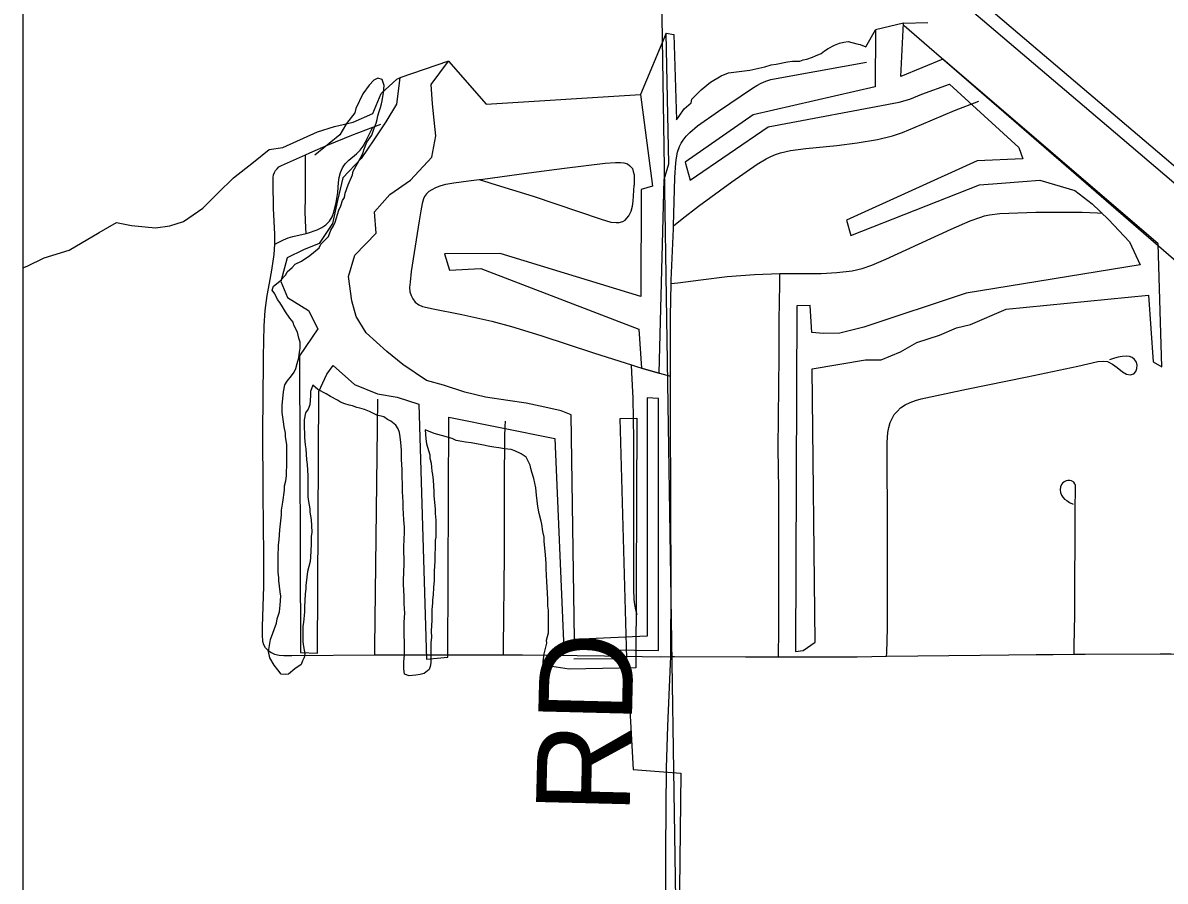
# Model space of a CAD drawing. Extents: x 0 to 34, y 0 to 22.
# Drawn here: x 2.1 to 2.4461, y 18.0054 to 18.2654 of the extents above; entities that cross this region are included whole.
import ezdxf

# ---------------------------------------------------------------- set-up
doc = ezdxf.new("R2010")
doc.units = 0
for name, color, linetype in [('GM_X_Corporation', 7, 'Continuous'), ('GM_X_Major_River', 7, 'Continuous'), ('GM_X_Minor_River', 7, 'Continuous'), ('GM_X_State_Route', 7, 'Continuous'), ('GM_X_Township_Road', 7, 'Continuous'), ('GM_X_Township_Road_Text', 7, 'Continuous')]:
    doc.layers.add(name, color=color, linetype=linetype)

msp = doc.modelspace()

# ---------------------------------------------------------------- linework, layer by layer
at = {"layer": 'GM_X_Corporation'}
for points in [[(2.1, 19.23555), (2.1, 16.59135)], [(3.00478, 18.43707), (2.97992, 18.42919), (2.92938, 18.42252), (2.66141, 18.41843), (2.5349, 18.41088), (2.48912, 18.40358), (2.36749, 18.37012), (2.29892, 18.34983), (2.2944, 18.34848), (2.29017, 18.34722), (2.28004, 18.34423), (2.20498, 18.31695), (2.13026, 18.28436), (2.1, 18.27405), (2.1, 16.59135)]]:
    msp.add_lwpolyline(points, dxfattribs=at)
for points in [[(2.1, 18.4508), (2.1, 17.94805), (2.29863, 17.94779), (2.29081, 18.44969)], [(2.29081, 18.44969), (2.80234, 18.44894), (2.79974, 17.94803), (2.29863, 17.94779)]]:
    msp.add_lwpolyline(points, close=True, dxfattribs=at)
at = {"layer": 'GM_X_Major_River'}
for p, q in [((2.29485, 18.26222), (2.28712, 18.24365)), ((2.36683, 18.26533), (2.35828, 18.2633)), ((2.22891, 18.25375), (2.21425, 18.24872))]:
    msp.add_line(p, q, dxfattribs=at)
for points in [[(2.36683, 18.26533), (2.37415, 18.26545)], [(2.28712, 18.24365), (2.29072, 18.21589), (2.28729, 18.21496), (2.28725, 18.18247), (2.24462, 18.1955), (2.22772, 18.19542), (2.22921, 18.19047), (2.2387, 18.19098), (2.28661, 18.17259), (2.28747, 18.16081), (2.29278, 18.15925), (2.29434, 18.21795), (2.2957, 18.22269), (2.29485, 18.26222)], [(2.29485, 18.26222), (2.29718, 18.26184), (2.298, 18.23604)], [(2.35825, 18.24599), (2.32125, 18.23753), (2.30065, 18.22323), (2.30212, 18.21771), (2.32579, 18.23389), (2.36552, 18.2414), (2.36876, 18.24233), (2.37238, 18.24382), (2.38075, 18.2468), (2.40169, 18.22766), (2.40299, 18.22423), (2.38913, 18.22357), (2.3495, 18.2056), (2.3508, 18.20103), (2.38983, 18.21634), (2.39648, 18.21686), (2.40294, 18.21739), (2.40807, 18.21773), (2.41868, 18.21462), (2.42397, 18.21059), (2.42887, 18.20581), (2.43527, 18.19911), (2.43845, 18.19206), (2.3858, 18.1835), (2.35477, 18.17326), (2.34755, 18.17141), (2.34261, 18.17126), (2.339, 18.17166), (2.33849, 18.17983), (2.3345, 18.17967), (2.33412, 18.07498), (2.33641, 18.07534), (2.34003, 18.07779), (2.33911, 18.16064), (2.35527, 18.16338), (2.36002, 18.16334), (2.36592, 18.16577), (2.37088, 18.16859), (2.37773, 18.17082), (2.38287, 18.17307), (2.38706, 18.17399), (2.39791, 18.17866), (2.44104, 18.18292), (2.44242, 18.16277), (2.44506, 18.16123), (2.444, 18.19848), (2.37872, 18.25442), (2.36596, 18.24919), (2.36683, 18.26533)], [(2.31154, 18.24933), (2.31381, 18.2503), (2.31704, 18.25069), (2.32026, 18.25109), (2.32386, 18.25186), (2.32481, 18.25206), (2.32671, 18.25264), (2.32823, 18.25283), (2.33164, 18.25361), (2.33316, 18.25381), (2.33543, 18.25382), (2.33638, 18.2542), (2.33752, 18.2544), (2.33922, 18.25498), (2.34017, 18.25536), (2.34188, 18.25613), (2.34282, 18.25689), (2.34396, 18.25766), (2.34585, 18.25862), (2.34737, 18.2592), (2.34869, 18.25958), (2.35002, 18.25978), (2.35268, 18.25903), (2.35363, 18.25885), (2.35534, 18.25809), (2.35828, 18.2633)], [(2.35828, 18.2633), (2.35825, 18.24599)], [(2.2661, 18.14671), (2.26307, 18.14787), (2.25815, 18.14904), (2.25246, 18.15022), (2.24696, 18.15102), (2.24013, 18.15202), (2.23388, 18.15358), (2.22744, 18.15571), (2.22232, 18.15708), (2.21514, 18.16188), (2.21023, 18.1659), (2.20401, 18.17146), (2.201, 18.17642), (2.19971, 18.18118), (2.19863, 18.18859), (2.20057, 18.19504), (2.20707, 18.20165), (2.20655, 18.20811), (2.21115, 18.2134), (2.21744, 18.21773), (2.22395, 18.22471), (2.22514, 18.23116), (2.2246, 18.23592), (2.22407, 18.24086), (2.22373, 18.24675), (2.22891, 18.25375)], [(2.22891, 18.25375), (2.24039, 18.24075), (2.28712, 18.24365)], [(2.21425, 18.24872), (2.21324, 18.24075), (2.20998, 18.23545), (2.20633, 18.22996), (2.20249, 18.22429), (2.19694, 18.21844), (2.19537, 18.21161), (2.1938, 18.20459), (2.18977, 18.19854), (2.18501, 18.19667), (2.18006, 18.19423), (2.17811, 18.18703), (2.18016, 18.18226), (2.18659, 18.17823), (2.1894, 18.1727)], [(2.18926, 18.23236), (2.1944, 18.23404), (2.2001, 18.23533), (2.20601, 18.23795), (2.20852, 18.24401), (2.21332, 18.2483), (2.21425, 18.24872)], [(2.298, 18.23604), (2.29888, 18.23711), (2.30039, 18.2394), (2.30247, 18.24112), (2.30265, 18.24226), (2.30548, 18.24513), (2.30832, 18.24742), (2.31154, 18.24933)], [(2.1, 18.19121), (2.10131, 18.19171), (2.10642, 18.1942), (2.114, 18.19652), (2.12309, 18.20188), (2.12839, 18.20495), (2.13295, 18.20402), (2.14016, 18.20329), (2.14453, 18.20389), (2.1487, 18.20524), (2.15456, 18.20925), (2.15909, 18.21384), (2.16382, 18.21842), (2.16987, 18.2232), (2.17459, 18.22702), (2.17877, 18.22761), (2.18926, 18.23236)], [(2.1894, 18.1727), (2.18383, 18.16457), (2.18413, 18.07469), (2.18925, 18.07446), (2.18964, 18.1537), (2.19214, 18.159), (2.19406, 18.16165), (2.20048, 18.1559), (2.20748, 18.153), (2.21336, 18.15201), (2.21999, 18.14987), (2.22228, 18.07272), (2.22874, 18.07324), (2.22907, 18.14601), (2.26112, 18.13952), (2.26388, 18.07566), (2.29255, 18.07527), (2.29253, 18.15165), (2.28911, 18.15187), (2.28916, 18.07966), (2.26713, 18.07868), (2.2661, 18.14671)]]:
    msp.add_lwpolyline(points, dxfattribs=at)
at = {"layer": 'GM_X_Minor_River'}
for points in [[(2.36701, 18.26457), (2.64872, 18.02059), (2.66169, 18.00811), (2.737, 17.94422), (2.75628, 17.92455), (2.77219, 17.89365), (2.65804, 17.86859), (2.54682, 17.86408), (2.47603, 17.86127), (2.42061, 17.8593)], [(2.17767, 18.10883), (2.17784, 18.11187), (2.17839, 18.11643), (2.17838, 18.11776), (2.17875, 18.12024), (2.1793, 18.12385), (2.17929, 18.12518), (2.17966, 18.1267), (2.17985, 18.12822), (2.18001, 18.1324), (2.17999, 18.13773), (2.17959, 18.14), (2.17959, 18.14114), (2.1792, 18.14304), (2.179, 18.14456), (2.17861, 18.14741), (2.1786, 18.1495), (2.17896, 18.15368), (2.17932, 18.15578), (2.18008, 18.15692), (2.1814, 18.15845), (2.18215, 18.15959), (2.18272, 18.16073), (2.18309, 18.16226), (2.18365, 18.16397), (2.18383, 18.16568), (2.18401, 18.16682), (2.184, 18.16872), (2.18362, 18.16986), (2.18323, 18.17176), (2.18208, 18.17384), (2.18188, 18.17479), (2.18093, 18.17593), (2.17959, 18.17782), (2.17863, 18.17934), (2.17787, 18.18067), (2.1771, 18.18161), (2.17634, 18.18332), (2.17557, 18.18446), (2.17594, 18.1856), (2.17783, 18.18713), (2.17972, 18.18904), (2.1801, 18.18999), (2.18161, 18.19133), (2.18255, 18.19228), (2.18445, 18.19324), (2.18691, 18.19496), (2.18974, 18.19726), (2.1903, 18.1984), (2.19257, 18.20069), (2.19332, 18.2026), (2.19407, 18.20393), (2.19464, 18.20507), (2.19576, 18.20869), (2.19632, 18.21002), (2.19688, 18.21154), (2.19745, 18.2125), (2.19763, 18.21383), (2.19857, 18.2163), (2.19988, 18.21935), (2.20006, 18.22049), (2.20138, 18.22278), (2.20307, 18.22602), (2.20326, 18.22697), (2.20419, 18.22925), (2.2057, 18.23135), (2.20645, 18.23345), (2.20701, 18.23497), (2.20739, 18.23611), (2.20757, 18.23725), (2.20794, 18.23858), (2.20832, 18.23973), (2.20869, 18.24087), (2.20888, 18.24182), (2.20924, 18.24429), (2.20942, 18.24638), (2.20884, 18.24828), (2.20751, 18.24865), (2.20638, 18.24808), (2.20487, 18.24655), (2.20298, 18.24388), (2.20091, 18.2395), (2.20054, 18.23817), (2.19809, 18.23493), (2.19677, 18.23264), (2.19602, 18.2315), (2.19489, 18.23054), (2.19394, 18.22977), (2.18843, 18.22532)], [(2.21544, 18.07195), (2.21562, 18.07385), (2.21557, 18.08392), (2.21575, 18.08658), (2.21554, 18.08943), (2.21553, 18.09171), (2.21532, 18.09532), (2.21532, 18.09646), (2.21548, 18.10159), (2.21546, 18.10673), (2.21562, 18.1111), (2.21561, 18.11262), (2.21541, 18.1149), (2.2152, 18.11851), (2.2152, 18.12022), (2.21499, 18.12345), (2.21496, 18.1301), (2.21475, 18.13314), (2.21473, 18.13599), (2.21453, 18.13827), (2.21434, 18.13998), (2.21414, 18.14131), (2.21375, 18.14245), (2.21299, 18.14358), (2.21146, 18.14472), (2.21051, 18.14528), (2.20937, 18.14604), (2.20728, 18.1466), (2.20499, 18.14773), (2.20347, 18.14829), (2.20214, 18.14866), (2.20119, 18.14885), (2.19986, 18.14941), (2.19891, 18.1496), (2.19758, 18.14997), (2.19625, 18.15054), (2.19529, 18.1511), (2.1932, 18.15223), (2.19187, 18.15299), (2.18939, 18.1543), (2.18787, 18.15563), (2.18712, 18.15372), (2.18713, 18.15239), (2.18695, 18.14973), (2.18639, 18.1484), (2.18563, 18.14725), (2.18526, 18.14516), (2.18527, 18.14402), (2.18529, 18.13984), (2.18549, 18.13756), (2.18569, 18.13642), (2.1859, 18.133), (2.18609, 18.13167), (2.1863, 18.12825), (2.18633, 18.12179), (2.18653, 18.12046), (2.18692, 18.11818), (2.18693, 18.11723), (2.18732, 18.11495), (2.18753, 18.11115), (2.18734, 18.10982), (2.18736, 18.10754), (2.18719, 18.10355), (2.187, 18.10222), (2.18626, 18.09918), (2.18608, 18.09746), (2.18571, 18.09499), (2.18572, 18.09404), (2.18554, 18.09233), (2.18537, 18.08853), (2.18537, 18.08701), (2.18501, 18.08378), (2.18483, 18.08263), (2.18484, 18.07921), (2.18485, 18.07788), (2.18505, 18.07655), (2.18544, 18.07428), (2.18525, 18.07313), (2.18469, 18.07218), (2.18432, 18.07104), (2.18242, 18.0697), (2.18053, 18.06817), (2.17959, 18.06798), (2.17826, 18.06816), (2.1773, 18.06948), (2.17615, 18.07081), (2.17481, 18.07308), (2.17443, 18.07498), (2.17498, 18.0786), (2.17685, 18.08355), (2.17703, 18.08488), (2.17778, 18.08697), (2.17796, 18.08906), (2.17813, 18.09173), (2.17794, 18.09305), (2.17754, 18.09647), (2.17754, 18.09742), (2.17734, 18.09894), (2.17731, 18.1035), (2.17749, 18.10731), (2.17767, 18.10883)], [(2.26691, 18.07276), (2.28302, 18.07284), (2.28094, 18.14561), (2.28606, 18.14564), (2.28569, 18.07), (2.2655, 18.06964)], [(2.2655, 18.06964), (2.25759, 18.07081), (2.25759, 18.07196), (2.25795, 18.07424), (2.2587, 18.07747), (2.25869, 18.07842), (2.25925, 18.0807), (2.25922, 18.08755), (2.25902, 18.08869), (2.25901, 18.09078), (2.2588, 18.09458), (2.25879, 18.0961), (2.25858, 18.10009), (2.25857, 18.10161), (2.25837, 18.10427), (2.25797, 18.10845), (2.25796, 18.10959), (2.25757, 18.1113), (2.25718, 18.11357), (2.25699, 18.11452), (2.25641, 18.1168), (2.25602, 18.11889), (2.25562, 18.12231), (2.25542, 18.12459), (2.25483, 18.12744), (2.25425, 18.12933), (2.25387, 18.13047), (2.25367, 18.13142), (2.25252, 18.13389), (2.251, 18.13483), (2.2491, 18.13577), (2.24796, 18.13615), (2.24587, 18.13633), (2.24416, 18.1367), (2.24264, 18.13688), (2.2415, 18.13707), (2.23903, 18.13762), (2.2358, 18.13818), (2.23409, 18.13836), (2.23295, 18.13855), (2.23124, 18.13892), (2.23009, 18.13948), (2.22686, 18.14042), (2.22458, 18.14098), (2.22192, 18.14211), (2.22212, 18.13945), (2.22232, 18.13793), (2.22329, 18.13451), (2.22329, 18.13356), (2.22368, 18.13204), (2.22388, 18.12957), (2.22408, 18.12862), (2.22427, 18.12691), (2.22448, 18.12349), (2.22449, 18.12216), (2.22489, 18.11817), (2.22489, 18.11684), (2.2251, 18.11475), (2.22512, 18.10962), (2.22494, 18.10867), (2.22495, 18.10696), (2.22477, 18.10373), (2.22478, 18.1024), (2.22461, 18.09936), (2.22462, 18.09651), (2.22444, 18.09441), (2.22426, 18.09213), (2.22408, 18.09061), (2.22409, 18.08966), (2.22391, 18.08776), (2.22392, 18.08453), (2.22375, 18.08111), (2.22376, 18.07921), (2.22358, 18.07769), (2.22361, 18.07161), (2.22343, 18.07046), (2.22305, 18.06951), (2.22154, 18.06836), (2.2204, 18.06798), (2.21907, 18.06778), (2.21699, 18.06758), (2.21565, 18.06815), (2.21545, 18.06986), (2.21544, 18.07195)], [(2.25939, 18.069), (2.25935, 18.06901)], [(2.28322, 18.06995), (2.2849, 18.03921), (2.29934, 18.03813), (2.29802, 17.9241)]]:
    msp.add_lwpolyline(points, dxfattribs=at)
at = {"layer": 'GM_X_State_Route'}
for points in [[(2.32715, 18.32565), (2.4035, 18.2607), (2.44374, 18.22642), (2.60957, 18.08537), (2.64991, 18.0512), (2.66881, 18.03502), (2.69927, 18.00908), (2.70884, 18.00091), (2.79294, 17.92908), (2.8025, 17.92113), (2.81117, 17.91424), (2.81841, 17.9089), (2.82651, 17.90318), (2.83267, 17.89916), (2.83668, 17.89664), (2.84237, 17.89321), (2.84916, 17.88924), (2.8572, 17.88476), (2.86534, 17.88048), (2.87342, 17.87642)], [(2.32427, 18.32289), (2.43302, 18.23041), (2.53238, 18.14581), (2.5762, 18.10862), (2.6425, 18.05228), (2.67326, 18.0261), (2.70357, 18.00047), (2.71553, 17.99031), (2.75061, 17.96052), (2.79287, 17.92439), (2.80271, 17.91643), (2.81262, 17.90855), (2.82077, 17.90255), (2.82865, 17.89695)]]:
    msp.add_lwpolyline(points, dxfattribs=at)
at = {"layer": 'GM_X_Township_Road'}
msp.add_line((2.20606, 18.23379), (2.20843, 18.23467), dxfattribs=at)
for points in [[(2.29944, 18.229), (2.30002, 18.22986), (2.30098, 18.23107), (2.30206, 18.23219), (2.30443, 18.23417), (2.31076, 18.23864), (2.32101, 18.24563), (2.32232, 18.24645), (2.32369, 18.24717), (2.32512, 18.24774), (2.3266, 18.24819), (2.33269, 18.24938), (2.35558, 18.25346)], [(2.29716, 18.20395), (2.29979, 18.20602), (2.30471, 18.20989), (2.3148, 18.21728), (2.32251, 18.22264), (2.3252, 18.22423), (2.3266, 18.22491), (2.32805, 18.22551), (2.32953, 18.22601), (2.33257, 18.22674), (2.33722, 18.2273), (2.34656, 18.22822), (2.35277, 18.22903), (2.35893, 18.23011), (2.36348, 18.23121), (2.36645, 18.23219), (2.37223, 18.23456), (2.38229, 18.23889), (2.38961, 18.24165)], [(2.18568, 18.22543), (2.18693, 18.22598), (2.19252, 18.22846), (2.1997, 18.23142), (2.20606, 18.23379)], [(2.18582, 18.20164), (2.18626, 18.20174), (2.18916, 18.20272), (2.19054, 18.2034), (2.19179, 18.20425), (2.19286, 18.20532), (2.19367, 18.2066), (2.19422, 18.20802), (2.19493, 18.211), (2.19538, 18.21402), (2.19564, 18.21706), (2.19586, 18.21857), (2.19623, 18.22006), (2.19681, 18.22147), (2.19765, 18.22272), (2.19871, 18.22381), (2.20111, 18.22571), (2.20218, 18.22679), (2.2031, 18.228), (2.2038, 18.22938), (2.20606, 18.23379)], [(2.29716, 18.20395), (2.29757, 18.21856), (2.29783, 18.22295), (2.298, 18.22451), (2.29835, 18.22618), (2.29898, 18.22791), (2.29944, 18.229)], [(2.17633, 18.19833), (2.17632, 18.20143), (2.17598, 18.2092), (2.17581, 18.21696), (2.17586, 18.21853), (2.17597, 18.21932), (2.1762, 18.22003), (2.17653, 18.22064), (2.17701, 18.22123), (2.1776, 18.22174), (2.17831, 18.22216), (2.18568, 18.22543)], [(2.18582, 18.20164), (2.18576, 18.20336), (2.18558, 18.20807), (2.18565, 18.21278), (2.18568, 18.22378), (2.18568, 18.22543)], [(2.23824, 18.21796), (2.2394, 18.2181), (2.25327, 18.21993), (2.26406, 18.22135), (2.2764, 18.22289), (2.2795, 18.22312), (2.28106, 18.2231), (2.28211, 18.22301), (2.28315, 18.22272), (2.28393, 18.22211), (2.28465, 18.22128), (2.28493, 18.22042), (2.28516, 18.21935), (2.28517, 18.21622)], [(2.22311, 18.21439), (2.22404, 18.21496), (2.2251, 18.21548), (2.2264, 18.216), (2.2281, 18.21649), (2.23054, 18.21695), (2.23506, 18.21756), (2.23824, 18.21796)], [(2.23824, 18.21796), (2.24121, 18.21703), (2.24212, 18.21675), (2.25456, 18.21288), (2.27517, 18.20594), (2.27817, 18.20505), (2.27971, 18.20488), (2.28067, 18.20493), (2.28177, 18.20522), (2.28252, 18.20568), (2.28357, 18.20693), (2.28426, 18.20832), (2.28466, 18.20984), (2.28489, 18.21138), (2.28517, 18.21622)], [(2.22311, 18.21439), (2.22229, 18.21361), (2.22165, 18.2128), (2.22137, 18.21211), (2.22096, 18.21068), (2.22057, 18.2085), (2.22002, 18.20543), (2.21769, 18.19004), (2.21731, 18.1869), (2.21717, 18.18528), (2.21726, 18.18396), (2.21762, 18.18285), (2.21819, 18.18177), (2.2189, 18.18079), (2.21993, 18.18004), (2.22109, 18.17953), (2.22251, 18.17916), (2.22381, 18.17887), (2.23298, 18.17711), (2.24205, 18.17503), (2.24804, 18.17344), (2.25695, 18.17073), (2.27317, 18.16535), (2.28436, 18.16181)], [(2.32933, 18.18945), (2.3419, 18.18951), (2.34656, 18.18975), (2.3512, 18.19031), (2.35423, 18.19099), (2.35717, 18.192), (2.36146, 18.19384), (2.38127, 18.2029), (2.38697, 18.20539), (2.38989, 18.20647), (2.39138, 18.2069), (2.3929, 18.20723), (2.39599, 18.20762), (2.40687, 18.20801), (2.42088, 18.2081), (2.42554, 18.2079), (2.42709, 18.20777)], [(2.29639, 18.18644), (2.29642, 18.18747), (2.29714, 18.203), (2.29716, 18.20395)], [(2.17633, 18.19833), (2.17894, 18.19965), (2.18034, 18.20026), (2.1818, 18.2007), (2.18582, 18.20164)], [(2.174, 18.18286), (2.17468, 18.1866), (2.17548, 18.19046), (2.17616, 18.19524), (2.17633, 18.19833)], [(2.29639, 18.18644), (2.29847, 18.18669), (2.30538, 18.1876), (2.31338, 18.18858), (2.32168, 18.18919), (2.32933, 18.18945)], [(2.32894, 18.07343), (2.32895, 18.07458), (2.32901, 18.08045), (2.329, 18.10671), (2.329, 18.12398), (2.32882, 18.13653), (2.32911, 18.16446), (2.32914, 18.17534), (2.32929, 18.18626), (2.32933, 18.18945)], [(2.29619, 18.15838), (2.29617, 18.16256), (2.29616, 18.17657), (2.29639, 18.18644)], [(2.17418, 18.07541), (2.17354, 18.0761), (2.17297, 18.07702), (2.17268, 18.07806), (2.17257, 18.08002), (2.17264, 18.08246), (2.17298, 18.09482), (2.17304, 18.1041), (2.17283, 18.12264), (2.17274, 18.14274), (2.17279, 18.15047), (2.17287, 18.16437), (2.17307, 18.17364), (2.17342, 18.17826), (2.174, 18.18286)], [(2.28607, 18.08613), (2.2857, 18.08765), (2.28543, 18.08919), (2.28525, 18.09074), (2.2851, 18.09386), (2.28511, 18.1392), (2.28485, 18.15172), (2.28447, 18.15953), (2.28436, 18.16181)], [(2.28436, 18.16181), (2.28652, 18.16112), (2.29401, 18.159), (2.29619, 18.15838)], [(2.3659, 18.14875), (2.36728, 18.14967), (2.36878, 18.15042), (2.37045, 18.15105), (2.37215, 18.15153), (2.3859, 18.15446), (2.40428, 18.15822), (2.41194, 18.15981), (2.41959, 18.1614), (2.4257, 18.16279), (2.42725, 18.16295), (2.4286, 18.16281), (2.43012, 18.16201), (2.43148, 18.16097), (2.4331, 18.1597), (2.43431, 18.15901), (2.43546, 18.15878), (2.43655, 18.15907), (2.43719, 18.15976), (2.43753, 18.16074), (2.43759, 18.16172), (2.43736, 18.16258), (2.43678, 18.16344), (2.43603, 18.16402), (2.43528, 18.16437), (2.43422, 18.16448), (2.433, 18.16439), (2.43187, 18.16418), (2.43077, 18.16387), (2.42919, 18.16335)], [(2.29628, 18.07348), (2.29631, 18.07547), (2.29641, 18.09413), (2.29624, 18.14701), (2.29619, 18.15838)], [(2.20663, 18.074), (2.20666, 18.07645), (2.20731, 18.13426), (2.20754, 18.15144)], [(2.36169, 18.07354), (2.36171, 18.07458), (2.36191, 18.08211), (2.36197, 18.11796), (2.36188, 18.13045), (2.36188, 18.13825), (2.36209, 18.14135), (2.36236, 18.14288), (2.36279, 18.14436), (2.36345, 18.14577), (2.364, 18.14673), (2.36493, 18.14782), (2.3659, 18.14875)], [(2.24562, 18.07401), (2.24565, 18.07621), (2.24593, 18.10424), (2.24591, 18.12615), (2.246, 18.14005), (2.24612, 18.14316), (2.24626, 18.14471)], [(2.41849, 18.07419), (2.41854, 18.0767), (2.41873, 18.08607), (2.41881, 18.11889), (2.41892, 18.12355), (2.41892, 18.12448), (2.4189, 18.12528), (2.41871, 18.12582), (2.41836, 18.12632), (2.41774, 18.12667), (2.41721, 18.12677), (2.41655, 18.12676), (2.41605, 18.12665), (2.41545, 18.1264), (2.41492, 18.12596), (2.41463, 18.12559), (2.41434, 18.12485), (2.41428, 18.124), (2.41436, 18.12312), (2.41466, 18.12237), (2.41503, 18.12176), (2.4156, 18.12118), (2.41628, 18.12068), (2.41705, 18.12017), (2.41824, 18.11961)], [(2.17418, 18.07541), (2.17522, 18.07472), (2.17619, 18.0742), (2.17769, 18.07386), (2.17902, 18.0738), (2.18147, 18.07374), (2.20663, 18.074)], [(2.20663, 18.074), (2.20943, 18.07403), (2.24562, 18.07401)], [(2.24562, 18.07401), (2.25137, 18.07401), (2.27621, 18.0737), (2.29329, 18.07343), (2.29628, 18.07348)], [(2.29439, 17.69525), (2.29419, 17.7052), (2.29418, 17.7208), (2.29441, 17.76126), (2.29469, 17.81351), (2.29475, 17.84993), (2.29472, 17.88882), (2.29475, 17.91059), (2.29471, 17.97127), (2.29482, 18.0148), (2.29504, 18.03974), (2.29539, 18.05234), (2.29625, 18.07129), (2.29628, 18.07348)], [(2.29628, 18.07348), (2.29746, 18.07348), (2.31891, 18.07343), (2.32894, 18.07343)], [(2.32894, 18.07343), (2.35273, 18.07343), (2.36169, 18.07354)], [(2.36169, 18.07354), (2.39004, 18.0739), (2.39874, 18.07402), (2.40703, 18.07407), (2.41215, 18.07408), (2.41849, 18.07419)], [(2.41849, 18.07419), (2.42183, 18.07419), (2.44457, 18.07425), (2.44785, 18.07425), (2.44958, 18.0742), (2.45054, 18.07404), (2.45154, 18.07368)]]:
    msp.add_lwpolyline(points, dxfattribs=at)

# ---------------------------------------------------------------- texts
at = {"layer": 'GM_X_Township_Road_Text'}
msp.add_text('RD', height=0.028409, rotation=88.5733, dxfattribs=at).set_placement((2.2838, 18.02561))

doc.saveas('drawing.dxf')
